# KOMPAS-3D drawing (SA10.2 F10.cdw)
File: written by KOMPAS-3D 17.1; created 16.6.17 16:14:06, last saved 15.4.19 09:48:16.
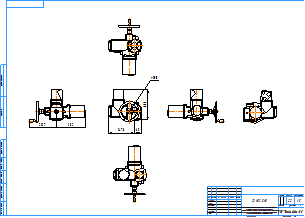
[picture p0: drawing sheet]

Sheet 1: A2, landscape

Title block, sheet 1: name: SA 10.2 F10; material: Сталь 20  ГОСТ 1050-88; mass: 22; sheets: 1; sheet format: A2; stored path: \\adlc.lan\data\АДЛ_ПКД\3D-модели\Поставщики\Сервоприводы AUMA\Электроприводы серии SA\KOMPAS 2D\SA 10.2 F10.cdw

Views: Спереди 1, Проекционный вид 3, Проекционный вид 4, Проекционный вид 6, Проекционный вид 5, Проекционный вид 2
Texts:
  Klimkovich
  ADL
  Рама для чертежей
  Лит-Масса-Масштаб
  Материал-Предприятие
  Масштаб
  Изм.
  Лист
  № докум.
  Подп.
  Дата
  Лит.
  Разраб.
  Пров.
  Т.контр.
  Листов
  Внимание! Данный продукт является объектом авторского права ООО «Торговый Дом АДЛ».
  Запрещается изменение, копирование, распространение
  (в том числе путем копирования на другие сайты и ресурсы в Интернете)
  или любое иное использование информации и объектов без предварительного
  согласия правообладателя (ООО «Торговый Дом АДЛ»).
  Н.контр.
  Утв.
  ООО "Торговый дом АДЛ"
  Изменение
  Номер документа
  Подпись
  Обозначение документа
  Наименование изделия
  Масса изделия по ГОСТ 2.109-73
  Порядковый номер листа
  Общее количество листов в документе
  Характер работы, выполненной лицом, подписавшим документ
  Наименование или индекс предприятия, выпускающего документ
  Инв. № подл.
  Подп. и дата
  Взам. инв. №
  Инв. № дубл.
  Инвентарный номер подлинника по ГОСТ 2.501-68
  Подпись принявшего подлинник в отдел технической документации
  Инвентарный номер подлинника, взамен которого выпущен данный подлинник
  Инвентарный номер дубликата по ГОСТ 2.502-68
  Подпись принявшего дубликат в отдел технической документации
  Справ. №
  Перв. примен.
  Обозначение документа, взамен или на основании которого выпущен данный документ
  Обозначение документа, в котором впервые записан данный документ
  Подпись лица, копировавшего чертеж
  Обозначение формата листа
  !Рама для чертежа
Dimensions and other numbers on the sheet: 200; 290; 247,8; 65; 253,7; 282; 1:5; 1; 22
